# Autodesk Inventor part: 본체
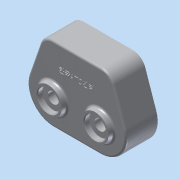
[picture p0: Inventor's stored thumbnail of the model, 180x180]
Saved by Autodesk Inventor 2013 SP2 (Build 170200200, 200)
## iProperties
Created: 2014-12
Part Number: 본체
Material: 알루미늄 6061
Document SubType Name: Modeling
Designer: dgall
Density: 2.71 g/cm^3
Mass: 613.443 g
Surface Area: 665.018 cm^2
Volume: 226.363 cm^3
Author: dgall
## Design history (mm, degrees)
sketch "스케치1"
  geometry: L1 (47, 36)-(-47, 36); L2 (-47, 36)-(-66.565, -20.803); L3 (-32.527, -68.527)-(32.527, -68.527); L4 (66.565, -20.803)-(47, 36); L5 (32.527, -32.527)-(0, 0); L6 (0, 0)-(-32.527, -32.527); A1 r 36 centre (-32.527, -32.527) between (-66.565, -20.803) and (-32.527, -68.527); A2 r 36 centre (32.527, -32.527) between (32.527, -68.527) and (66.565, -20.803); 2 further points
  constraints: 12 end point, 4 point on circle, 4 tangent, 2 centre point, 2 midpoint, 2 vertical alignment, 1 equal length, 1 equal radius, 1 horizontal, 1 parallel
  dimensions: "d0" = 90 deg angle of L6 L5; "d1" = 36 radius of A1; "d3" = 94 distance of L1.start L1.end; "d4" = 36 distance from line of L5.end L1; "d5" = 46 distance of L5.start L5.end
extrude "돌출1" new body sketch "스케치1" distance "d6" = 44; taper "d7" = 0 deg
sketch "스케치2"
  geometry: L1 (-47, -36)-(47, -36) reference; L2 (47, -36)-(66.565, 20.803) reference; L3 (32.527, 68.527)-(-32.527, 68.527) reference; L4 (-66.565, 20.803)-(-47, -36) reference; L5 (-32.527, 63.527)-(32.527, 63.527); L6 (61.837, 22.432)-(43.434, -31); L7 (43.434, -31)-(-43.434, -31); L8 (-43.434, -31)-(-61.837, 22.432); A1 r 36 centre (32.527, 32.527) between (66.565, 20.803) and (32.527, 68.527) reference; A2 r 36 centre (-32.527, 32.527) between (-32.527, 68.527) and (-66.565, 20.803) reference; A3 r 31 centre (32.527, 32.527) between (61.837, 22.432) and (32.527, 63.527); A4 r 31 centre (-32.527, 32.527) between (-32.527, 63.527) and (-61.837, 22.432); 1 further point
  constraints: 8 end point, 4 point on circle, 2 centre point, 5 other
  dimensions: "d8" = 5 distance between parallel lines of L1 L7
extrude "돌출2" cut sketch "스케치2" distance "d9" = 34; taper "d10" = 0 deg
sketch "스케치3"
  geometry: A1 r 31 centre (-32.527, 32.527) between (-32.527, 63.527) and (-61.837, 22.432) reference; A2 r 31 centre (32.527, 32.527) between (61.837, 22.432) and (32.527, 63.527) reference; A3 r 24 centre (32.527, 32.527) between (21.111, 11.416) and (11.416, 21.111); A4 r 24 centre (-32.527, 32.527) between (-11.416, 21.111) and (-21.111, 11.416); A5 r 24 centre (0, 0) between (11.416, 21.111) and (-11.416, 21.111); A6 r 24 centre (0, 0) between (-21.111, 11.416) and (21.111, 11.416); 1 further point
  constraints: 8 point on circle, 4 centre point, 3 coincident, 3 equal radius
  dimensions: "d13" = 24 radius of A6
extrude "돌출3" join sketch "스케치3" distance "d17" = 11; taper "d18" = 0 deg
hole "구멍1" diameter "d21" = 20; stored, may be unused: countersink angle "d25" = 90 deg, drill point angle "d27" = 0 deg; dims "d19" = 10, "d20" = 10, "d22" = 6, "d23" = 40, "d24" = 12, "d26" = 15
hole "구멍2" diameter "d30" = 15.5; stored, may be unused: countersink angle "d34" = 90 deg, drill point angle "d36" = 0 deg; dims "d28" = 10, "d29" = 10, "d31" = 6, "d32" = 35, "d33" = 11, "d35" = 21
hole "구멍3" diameter "d39" = 15.5; stored, may be unused: countersink angle "d43" = 90 deg, drill point angle "d45" = 0 deg; dims "d37" = 10, "d38" = 10, "d40" = 6, "d41" = 35, "d42" = 11, "d44" = 21
sketch "스케치4"
  geometry: L1 (-32.527, 63.527)-(32.527, 63.527) reference; L2 (61.837, 22.432)-(43.434, -31) reference; L3 (-43.434, -31)-(-61.837, 22.432) reference; L4 (-47, -36)-(47, -36) reference; A1 r 8 centre (-51.7, -7) between (-49.095, -14.564) and (-54.305, 0.564); A2 r 8 centre (51.7, -7) between (54.305, 0.564) and (49.095, -14.564); A3 r 8 centre (0, 63.527) between (-8, 63.527) and (8, 63.527); 1 further point
  constraints: 8 point on line, 6 point on circle, 3 centre point, 2 equal radius, 1 midpoint
  dimensions: "d69" = 29 distance from line of A1.centre L4; "d70" = 8 radius of A1; "d71" = 29 distance from line of A2.centre L4
extrude "돌출4" join sketch "스케치4" distance "d72" = 34; taper "d73" = 0 deg
hole "구멍6" diameter "d76" = 4.134; stored, may be unused: countersink angle "d80" = 90 deg, drill point angle "d82" = 118 deg; dims "d74" = 10, "d75" = 10, "d77" = 20, "d78" = 35, "d79" = 11, "d81" = 23
hole "구멍7" diameter "d85" = 4.134; stored, may be unused: countersink angle "d89" = 90 deg, drill point angle "d91" = 118 deg; dims "d83" = 10, "d84" = 10, "d86" = 20, "d87" = 35, "d88" = 11, "d90" = 23
hole "구멍8" diameter "d94" = 4.134; stored, may be unused: countersink angle "d98" = 90 deg, drill point angle "d100" = 118 deg; dims "d92" = 10, "d93" = 10, "d95" = 20, "d96" = 35, "d97" = 11, "d99" = 23
sketch "스케치5"
  geometry: C1 r 7.75 at (32.527, -32.527) reference; C2 r 7.75 at (-32.527, -32.527) reference; C3 r 20 at (-32.527, -32.527); C4 r 20 at (32.527, -32.527); A1 r 36 centre (-32.527, -32.527) between (-66.565, -20.803) and (-32.527, -68.527) reference; A2 r 36 centre (32.527, -32.527) between (32.527, -68.527) and (66.565, -20.803) reference; 1 further point
  constraints: 2 centre point, 2 coincident
  dimensions: "d101" = 40 diameter of C3; "d104" = 40 diameter of C4
extrude "돌출5" join sketch "스케치5" distance "d105" = 7; taper "d106" = -10 deg
hole "구멍9" diameter "d109" = 30; stored, may be unused: countersink angle "d113" = 90 deg, drill point angle "d115" = 0 deg; dims "d107" = 10, "d108" = 10, "d110" = 20, "d111" = 35, "d112" = 11, "d114" = 7
hole "구멍10" diameter "d118" = 30; stored, may be unused: countersink angle "d122" = 90 deg, drill point angle "d124" = 0 deg; dims "d116" = 10, "d117" = 10, "d119" = 20, "d120" = 35, "d121" = 11, "d123" = 7
chamfer "모따기1" distance "d64" = 1; stored, may be unused: second distance "d65" = 2, angle "d66" = 45 deg
fillet "모깎기1" dims "d125" = 18, "d126" = 13
fillet "모깎기2" dims "d127" = 3
fillet "모깎기3" dims "d128" = 3
fillet "모깎기4" dims "d129" = 3
fillet "모깎기5" dims "d130" = 0.3, "d135" = 0.1
node "작업 평면1"
sketch "스케치6"
  geometry: L1 (34.162, 36)-(-34.162, 36) reference; 2 further points
  constraints: 1 vertical alignment, 1 other
  dimensions: "d132" = 30 distance from line of point (0, 6) L1
feature "엠보싱1" sketch "스케치6" dims "d0" = 90 deg, "d1" = 36, "d3" = 94, "d4" = 36, "d5" = 46, "d8" = 5, "d133" = 1, "d134" = 0
node "솔리드1"
other parameters: "d11" = 48, "d131" = 15.75
